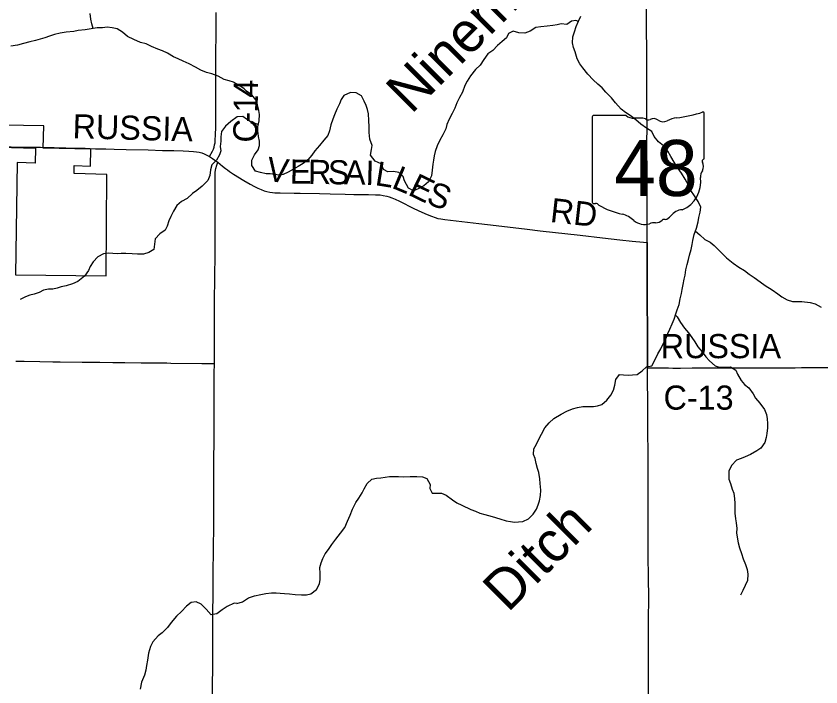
# Model space of a CAD drawing. Extents: x -87 to 2145, y -2128 to 440.
# Drawn here: x -9.26 to 40.7, y -1010.07 to -968.4 of the extents above; entities that cross this region are included whole.
import ezdxf

# ---------------------------------------------------------------- set-up
doc = ezdxf.new("R2010")
doc.units = 0
for name, color, linetype in [('GM_X_County_Road', 7, 'Continuous'), ('GM_X_County_Road_Text', 7, 'Continuous'), ('GM_X_County_Subdivision_Text', 7, 'Continuous'), ('GM_X_Minor_River', 7, 'Continuous'), ('GM_X_Minor_River_Text', 7, 'Continuous'), ('GM_X_State_Location', 7, 'Continuous'), ('GM_X_State_Route', 7, 'Continuous'), ('GM_X_State_Shield', 7, 'Continuous'), ('GM_X_Township_Road', 7, 'Continuous')]:
    doc.layers.add(name, color=color, linetype=linetype)

msp = doc.modelspace()

# ---------------------------------------------------------------- linework, layer by layer
at = {"layer": 'GM_X_County_Road'}
for points in [[(2.749, -977.127), (2.941, -976.786), (2.993, -976.663), (3.035, -976.537), (3.067, -976.408), (3.09, -976.277), (3.108, -976.096), (3.123, -975.8), (3.134, -975.274), (3.146, -973.896), (3.146, -972.863), (3.147, -972.223), (3.144, -971.304), (3.151, -970.501), (3.153, -969.763), (3.159, -968.697), (3.163, -968.172)], [(-15.533, -976.482), (-14.481, -976.477), (-13.497, -976.485), (-12.774, -976.489), (-11.478, -976.497), (-10.69, -976.507), (-9.558, -976.524), (-8.672, -976.537), (-7.737, -976.554), (-7.575, -976.558)], [(-7.575, -976.558), (-6.9, -976.575), (-5.423, -976.607), (-4.98, -976.617), (-4.324, -976.641), (-3.685, -976.659), (-3.176, -976.671), (-2.422, -976.693), (-1.06, -976.716), (-0.174, -976.746), (0.531, -976.76), (1.105, -976.776), (1.467, -976.789), (1.746, -976.807), (1.943, -976.831), (2.106, -976.862), (2.266, -976.906), (2.407, -976.956), (2.581, -977.038), (2.749, -977.127)], [(2.749, -977.127), (2.94, -977.243), (3.145, -977.39), (3.26, -977.482)], [(3.05, -989.978), (3.053, -989.142), (3.062, -988.043), (3.064, -987.288), (3.066, -986.386), (3.085, -984.402), (3.095, -983.434), (3.096, -982.236), (3.104, -981.006), (3.107, -979.317), (3.104, -978.332), (3.108, -978.121), (3.123, -977.976), (3.145, -977.866), (3.206, -977.663), (3.26, -977.482)], [(3.26, -977.482), (3.554, -977.719), (3.733, -977.863), (3.865, -977.962), (3.999, -978.057), (4.246, -978.22), (4.874, -978.609), (5.268, -978.846), (5.542, -978.998), (5.749, -979.1), (5.946, -979.184), (6.134, -979.249), (6.308, -979.299), (6.486, -979.338), (6.65, -979.364), (6.798, -979.377), (7.127, -979.386), (7.996, -979.395), (8.373, -979.402), (9.57, -979.431), (10.242, -979.452), (11.177, -979.469), (11.702, -979.479), (12.194, -979.487), (12.621, -979.491), (13.063, -979.497), (13.339, -979.513), (13.532, -979.539), (13.754, -979.589), (13.91, -979.634), (14.063, -979.689), (14.274, -979.777), (14.541, -979.901), (15.436, -980.348), (15.925, -980.583), (16.27, -980.737), (16.529, -980.842), (16.747, -980.919), (16.922, -980.968), (17.116, -981.008), (17.361, -981.044), (18.404, -981.165), (19.462, -981.297), (20.538, -981.417), (22.459, -981.65), (23.274, -981.739), (25.768, -982.018), (27.137, -982.178), (28.229, -982.301), (28.979, -982.383), (29.697, -982.454), (29.918, -982.476)], [(29.918, -982.476), (29.92, -983.466), (29.918, -984.336), (29.92, -984.992), (29.927, -985.812), (29.928, -986.451), (29.933, -987.649), (29.944, -988.698), (29.946, -990.254)], [(2.931, -1011.039), (2.94, -1009.957), (2.956, -1008.874), (2.955, -1008.004), (2.957, -1006.315), (2.965, -1005.331), (2.975, -1004.478), (2.98, -1003.297), (2.985, -1002.855), (2.995, -1001.706), (3.003, -1001.017), (3.007, -1000.525), (3.014, -999.738), (3.019, -997.671), (3.027, -996.654), (3.025, -995.785), (3.03, -994.981), (3.028, -994.472), (3.029, -994.128), (3.03, -993.981), (3.032, -993.079), (3.045, -991.734), (3.048, -990.602), (3.05, -989.978)], [(29.946, -990.254), (30.112, -990.255), (30.801, -990.259), (31.244, -990.263), (31.506, -990.264), (31.981, -990.265), (32.719, -990.258), (33.818, -990.258), (34.474, -990.255), (35.262, -990.254), (35.803, -990.258), (36.459, -990.254), (37.164, -990.25), (38.443, -990.248), (39.099, -990.247), (39.493, -990.242), (40.182, -990.24), (41.182, -990.232)]]:
    msp.add_lwpolyline(points, dxfattribs=at)
at = {"layer": 'GM_X_County_Subdivision_Text'}
msp.add_lwpolyline([(-10.304, -976.556), (-8.061, -976.603), (-8.069, -977.537), (-9.194, -977.506), (-9.291, -984.466), (-3.677, -984.536), (-3.628, -978.245), (-5.656, -978.19), (-5.643, -977.691), (-4.643, -977.717), (-4.615, -976.674), (-7.576, -976.613), (-7.539, -975.225), (-12.623, -975.146)], dxfattribs=at)
at = {"layer": 'GM_X_Minor_River'}
for points in [[(-4.478, -969.174), (-4.562, -968.89), (-4.617, -968.587), (-4.66, -968.244)], [(25.654, -968.738), (25.498, -968.675), (25.226, -968.72), (24.94, -968.936), (24.58, -968.888), (24.327, -968.943), (24.065, -968.988), (23.703, -969.031), (23.311, -969.063), (23.008, -969.107), (22.662, -969.341), (22.328, -969.465), (21.957, -969.448), (21.597, -969.339), (21.303, -969.494), (21.177, -969.754), (20.921, -969.98), (20.635, -970.236), (20.347, -970.542), (20.031, -970.757), (19.773, -971.104), (19.545, -971.452), (19.268, -971.729), (18.958, -972.125), (18.741, -972.453), (18.595, -972.712), (18.455, -973.122), (18.278, -973.461), (18.11, -973.79), (17.972, -974.129), (17.815, -974.448), (17.627, -974.817), (17.489, -975.137), (17.413, -975.417), (17.235, -975.776), (17.057, -976.105), (16.889, -976.464), (16.761, -976.814), (16.695, -977.084), (16.65, -977.355), (16.614, -977.606), (16.566, -977.978), (16.529, -978.32), (16.35, -978.699), (16.044, -978.954), (15.709, -979.129), (15.405, -979.253), (15.107, -979.086), (14.855, -978.637), (14.761, -978.363), (14.504, -978.126), (14.174, -978.059), (13.812, -978.082), (13.554, -977.935), (13.411, -977.58), (13.033, -977.411), (12.75, -977.042), (12.797, -976.7), (12.842, -976.45), (12.7, -976.054), (12.658, -975.64), (12.656, -975.277), (12.644, -974.894), (12.612, -974.48), (12.557, -974.217), (12.482, -973.964), (12.357, -973.699), (12.184, -973.353), (11.856, -973.175), (11.495, -973.147), (11.09, -973.33), (10.924, -973.589), (10.818, -973.849), (10.66, -974.188), (10.502, -974.537), (10.396, -974.797), (10.288, -975.167), (10.2, -975.528), (10.094, -975.818), (9.846, -976.115), (9.569, -976.441), (9.29, -976.778), (9.094, -977.036), (8.847, -977.333), (8.561, -977.559), (8.256, -977.744), (7.961, -977.919), (7.626, -978.103), (7.311, -978.248), (7.059, -978.283), (6.799, -978.247), (6.519, -978.211), (6.268, -978.196), (5.918, -978.118), (5.609, -978.031), (5.375, -977.683), (5.382, -977.351), (5.539, -977.032), (5.767, -976.704), (5.853, -976.444), (5.848, -976.172)], [(27.907, -991.32), (27.964, -990.969), (28.191, -990.671), (28.452, -990.697), (28.763, -990.703), (29.014, -990.688), (29.296, -990.664), (29.612, -990.429), (29.879, -990.182), (30.211, -990.119), (30.41, -989.73), (30.588, -989.381), (30.766, -989.063), (30.944, -988.684), (31.101, -988.405), (31.207, -988.115), (31.333, -987.856), (31.471, -987.516), (31.588, -987.227), (31.705, -986.897), (31.78, -986.646), (31.898, -986.327), (31.975, -985.976), (32.042, -985.645), (32.098, -985.384), (32.155, -985.083), (32.222, -984.752), (32.267, -984.491), (32.325, -984.16), (32.392, -983.829), (32.478, -983.528), (32.544, -983.248), (32.642, -982.897), (32.709, -982.596), (32.754, -982.346), (32.842, -981.965), (32.981, -981.585), (33.08, -981.194), (33.135, -980.923), (33.203, -980.592), (33.259, -980.281), (33.076, -979.925), (32.852, -979.577), (32.638, -979.241), (32.494, -978.915), (32.282, -978.528), (32.048, -978.161), (31.794, -977.813), (31.591, -977.476), (31.397, -977.119), (31.203, -976.803), (30.929, -976.455), (30.613, -976.217), (30.358, -975.889), (30.215, -975.564), (29.877, -975.365), (29.531, -975.126), (29.215, -974.848), (28.869, -974.579), (28.572, -974.401), (28.305, -974.184), (27.962, -973.794), (27.707, -973.486), (27.353, -973.126), (27.128, -972.87), (26.862, -972.623), (26.566, -972.365), (26.232, -972.005), (25.928, -971.626), (25.743, -971.36), (25.579, -971.065), (25.447, -970.629), (25.342, -970.365), (25.278, -970.061), (25.306, -969.689), (25.413, -969.389), (25.52, -969.049), (25.657, -968.729), (25.805, -968.4)], [(5.039, -973.073), (4.892, -972.916), (4.575, -972.698), (4.237, -972.51), (3.978, -972.424), (3.649, -972.337), (3.281, -972.139), (2.903, -972), (2.553, -971.913), (2.215, -971.755), (1.888, -971.567), (1.49, -971.368), (1.112, -971.209), (0.794, -971.052), (0.515, -970.945), (0.148, -970.716), (-0.18, -970.559), (-0.469, -970.452), (-0.857, -970.294), (-1.175, -970.136), (-1.534, -970.048), (-1.942, -969.869), (-2.34, -969.68), (-2.656, -969.402), (-2.983, -969.194), (-3.303, -969.127), (-3.613, -969.101), (-3.885, -969.136), (-4.226, -969.139), (-4.478, -969.174), (-4.961, -969.266), (-5.403, -969.307), (-5.675, -969.352), (-6.158, -969.403), (-6.53, -969.456), (-6.873, -969.54), (-7.186, -969.645), (-7.469, -969.75), (-7.762, -969.845), (-8.044, -969.93), (-8.397, -970.014), (-8.801, -970.117), (-9.173, -970.201), (-9.586, -970.263)], [(5.848, -976.172), (5.794, -975.889), (5.741, -975.535), (5.746, -975.284), (5.825, -974.902), (5.843, -974.52), (5.818, -974.268), (5.735, -973.923), (5.621, -973.609), (5.366, -973.291), (5.039, -973.073)], [(5.043, -974.816), (4.808, -974.637), (4.457, -974.661), (4.08, -974.956), (3.733, -975.241), (3.496, -975.569), (3.459, -975.911), (3.444, -976.173), (3.417, -976.515), (3.442, -976.767), (3.377, -977.028), (3.19, -977.347), (2.903, -977.653), (2.817, -977.964), (2.77, -978.296), (2.654, -978.616), (2.296, -978.962), (1.959, -979.237), (1.695, -979.433), (1.358, -979.729), (1.013, -979.924), (0.717, -980.18), (0.519, -980.529), (0.343, -980.848), (0.227, -981.118), (0.12, -981.448), (0.005, -981.708), (-0.331, -981.933), (-0.618, -982.23), (-0.665, -982.581), (-0.711, -982.903), (-1.016, -983.089), (-1.359, -983.183), (-1.72, -983.196), (-2.061, -983.179), (-2.441, -983.141), (-2.743, -983.155), (-2.994, -983.17), (-3.244, -983.155), (-3.525, -983.13), (-3.827, -983.164), (-4.192, -983.359), (-4.479, -983.665), (-4.655, -983.954), (-4.76, -984.214), (-5.018, -984.552), (-5.426, -984.896), (-5.75, -985.041), (-6.143, -985.164), (-6.456, -985.229), (-6.718, -985.314), (-6.97, -985.36), (-7.241, -985.374), (-7.553, -985.419), (-7.817, -985.565), (-8.14, -985.669), (-8.402, -985.744), (-8.665, -985.84), (-9.01, -986.015)], [(5.777, -975.132), (5.65, -975.09), (5.341, -974.993), (5.043, -974.816)], [(32.916, -981.763), (33.193, -981.992), (33.488, -982.29), (33.827, -982.438), (34.083, -982.655), (34.516, -983.087), (34.84, -983.427), (35.266, -983.748), (35.602, -983.996), (35.969, -984.216), (36.245, -984.433), (36.562, -984.651), (36.938, -984.921), (37.245, -985.139), (37.681, -985.41), (38.028, -985.659), (38.285, -985.845), (38.602, -986.023), (38.931, -986.141), (39.203, -986.136), (39.514, -986.133), (40.035, -986.204), (40.345, -986.271), (40.722, -986.49)], [(31.678, -986.972), (31.781, -987.09), (31.995, -987.447), (32.239, -987.784), (32.474, -988.071), (32.698, -988.368), (32.874, -988.633), (33.068, -988.94), (33.342, -989.268), (33.567, -989.564), (33.783, -989.821), (34.138, -990.13), (34.397, -990.206), (34.749, -990.203), (35.101, -990.191), (35.418, -990.388), (35.533, -990.643), (35.746, -991.03), (35.962, -991.286), (36.238, -991.503), (36.502, -991.861), (36.647, -992.136), (36.911, -992.444), (37.194, -992.843), (37.318, -993.147), (37.373, -993.42), (37.397, -993.703), (37.391, -993.985), (37.354, -994.336), (37.298, -994.587), (37.232, -994.898), (36.973, -995.235), (36.719, -995.411), (36.342, -995.635), (36.008, -995.779), (35.745, -995.884), (35.462, -995.979), (35.163, -996.315), (34.995, -996.664), (34.98, -996.916), (34.985, -997.177), (35.09, -997.431), (35.203, -997.786), (35.288, -998.04), (35.331, -998.393), (35.365, -998.656), (35.369, -998.978), (35.362, -999.29), (35.395, -999.623), (35.45, -999.876), (35.483, -1000.229), (35.467, -1000.51), (35.502, -1000.763), (35.565, -1001.117), (35.658, -1001.441), (35.782, -1001.776), (35.885, -1002.11), (36.028, -1002.475), (36.123, -1002.779), (36.157, -1003.062), (36.149, -1003.454), (36.011, -1003.774), (35.864, -1004.093), (35.718, -1004.372)], [(4.444, -1004.888), (4.787, -1004.795), (5.164, -1004.541), (5.549, -1004.418), (5.942, -1004.336), (6.255, -1004.262), (6.587, -1004.218), (6.888, -1004.225), (7.139, -1004.24), (7.41, -1004.266), (7.72, -1004.292), (8.071, -1004.34), (8.452, -1004.348), (8.764, -1004.344), (9.036, -1004.29), (9.383, -1004.015), (9.581, -1003.677), (9.617, -1003.406), (9.615, -1003.033), (9.593, -1002.65), (9.689, -1002.36), (9.775, -1002.09), (9.922, -1001.801), (10.128, -1001.544), (10.346, -1001.226), (10.594, -1000.889), (10.883, -1000.512), (11.141, -1000.175), (11.32, -999.776), (11.478, -999.407), (11.617, -999.027), (11.836, -998.619), (12.013, -998.35), (12.22, -998.022), (12.346, -997.763), (12.544, -997.435), (12.831, -997.159), (13.123, -997.105), (13.385, -997.08), (13.647, -997.035), (13.919, -997), (14.21, -996.996), (14.491, -997.012), (14.782, -997.018), (15.204, -996.997), (15.616, -996.996), (15.977, -997.033), (16.246, -997.13), (16.439, -997.496), (16.434, -997.748), (16.569, -998.033), (16.9, -998.04), (17.151, -998.035), (17.439, -998.172), (17.835, -998.462), (18.102, -998.639), (18.411, -998.786), (18.968, -999.05), (19.266, -999.166), (19.535, -999.283), (19.835, -999.36), (20.294, -999.49), (20.763, -999.641), (21.162, -999.76), (21.432, -999.806), (21.683, -999.841), (21.934, -999.826), (22.196, -999.802), (22.541, -999.628), (22.848, -999.352), (23.045, -999.034), (23.151, -998.764), (23.237, -998.514), (23.304, -998.173), (23.311, -997.851), (23.28, -997.427), (23.245, -997.145), (23.183, -996.761), (23.108, -996.497), (23.034, -996.194), (22.961, -995.88), (22.866, -995.626), (22.873, -995.274), (23.04, -994.985), (23.217, -994.646), (23.364, -994.378), (23.563, -993.979), (23.84, -993.672), (24.117, -993.396), (24.585, -993.134), (24.93, -992.94), (25.275, -992.806), (25.598, -992.722), (25.931, -992.648), (26.593, -992.662), (26.845, -992.617), (27.108, -992.522), (27.405, -992.266), (27.672, -991.96), (27.83, -991.63), (27.907, -991.32)], [(4.444, -1004.888), (4.27, -1004.865), (3.854, -1005.068), (3.539, -1005.283), (3.193, -1005.538), (2.851, -1005.592), (2.536, -1005.253), (2.221, -1004.935), (1.913, -1004.788), (1.611, -1004.832), (1.316, -1005.058), (1.018, -1005.385), (0.692, -1005.68), (0.373, -1006.067), (0.136, -1006.375), (-0.181, -1006.711), (-0.436, -1006.897), (-0.774, -1007.273), (-0.911, -1007.572), (-1.029, -1007.983), (-1.108, -1008.404), (-1.164, -1008.736), (-1.21, -1009.027), (-1.296, -1009.337), (-1.465, -1009.777), (-1.554, -1010.208)]]:
    msp.add_lwpolyline(points, dxfattribs=at)
at = {"layer": 'GM_X_State_Route'}
for points in [[(29.918, -982.244), (29.916, -981.498), (29.917, -980.366), (29.91, -979.399), (29.911, -978.89), (29.912, -978.004), (29.904, -976.758), (29.905, -976.217), (29.909, -975.364), (29.901, -974.264), (29.899, -972.854), (29.899, -971.64), (29.892, -970.492), (29.883, -969.245), (29.88, -968.426), (29.885, -967.54), (29.884, -966.113), (29.879, -964.85), (29.874, -963.685), (29.876, -963.474)], [(29.918, -982.476), (29.918, -982.351), (29.918, -982.244)], [(29.946, -990.254), (29.944, -988.698), (29.933, -987.649), (29.928, -986.451), (29.927, -985.812), (29.92, -984.992), (29.918, -984.336), (29.92, -983.466), (29.918, -982.476)], [(30.002, -1010.841), (29.998, -1010.054), (29.997, -1009.021), (30.002, -1007.364), (30.003, -1006.15), (30.015, -1004.296), (30.005, -1003.525), (29.983, -1001.656), (29.981, -1000.491), (29.974, -998.277), (29.975, -996.932), (29.973, -996.276), (29.971, -995.275), (29.969, -994.488), (29.963, -993.176), (29.953, -992.11), (29.948, -991.273), (29.946, -990.273), (29.946, -990.254)]]:
    msp.add_lwpolyline(points, dxfattribs=at)
at = {"layer": 'GM_X_State_Shield'}
for p, q in [((26.506, -974.671), (26.506, -979.954)), ((28.613, -974.58), (26.574, -974.58)), ((33.466, -977.213), (33.466, -974.449)), ((33.466, -977.212), (33.466, -977.213))]:
    msp.add_line(p, q, dxfattribs=at)
for centre, radius, start, end in [((26.585, -974.659), 0.0806, 98.1301, 188.1301), ((29.098, -973.966), 0.782, 231.6195, 271.1119), ((29.357, -977.546), 2.808, 80.4867, 94.9883), ((31.928, -976.193), 1.485, 97.3462, 120.7689), ((30.987, -967.377), 7.382, 275.8445, 288.9065), ((33.389, -974.437), 0.0775, 351.8621, 97.738), ((29.995, -974.632), 0.226, 219.7921, 297.1024), ((30.326, -975.243), 0.469, 54.4667, 119.1411), ((30.932, -974.405), 0.564, 233.8562, 294.8282), ((33.384, -977.223), 0.0829, 289.6038, 7.7341), ((33.448, -977.415), 0.12, 107.944, 210.337), ((32.686, -977.765), 0.72, 340.033, 23.6496), ((33.744, -978.369), 0.524, 136.8065, 186.9296), ((31.4, -978.721), 1.846, 292.3089, 8.9858), ((26.586, -979.965), 0.0814, 171.9584, 258.3066), ((26.598, -979.425), 0.621, 267.339, 280.6039), ((26.725, -980.259), 0.224, 29.7484, 93.2717), ((29.552, -975.512), 5.331, 240.4129, 257.1985), ((27.963, -982.327), 1.668, 47.1842, 75.836), ((32.179, -981.437), 1.011, 94.4031, 142.5768), ((29.766, -980.285), 1.058, 230.7004, 286.2918), ((30.378, -982.111), 0.87, 85.6951, 111.2099), ((30.455, -980.681), 0.564, 268.777, 315.5493), ((30.965, -981.192), 0.159, 65.7517, 132.6484), ((30.898, -980.466), 0.597, 282.8732, 323.2771)]:
    msp.add_arc(centre, radius, start, end, dxfattribs=at)
at = {"layer": 'GM_X_Township_Road'}
msp.add_lwpolyline([(-9.272, -989.846), (-8.747, -989.847), (-7.795, -989.859), (-6.976, -989.873), (-6.516, -989.877), (-5.155, -989.892), (-4.056, -989.903), (-3.252, -989.915), (-3.022, -989.918), (-2.793, -989.921), (-2.498, -989.925), (-1.497, -989.934), (-0.398, -989.948), (0.094, -989.952), (0.34, -989.956), (2.276, -989.974), (2.75, -989.976), (2.913, -989.977), (3.05, -989.978)], dxfattribs=at)

# ---------------------------------------------------------------- texts
at = {"layer": 'GM_X_County_Road_Text'}
for s, rotation, p in [('4', 89.6157, (5.75, -973.477)), ('1', 89.5847, (5.743, -974.402)), ('RUSSIA', 358.4567, (-5.765, -975.992)), ('-', 89.4935, (5.738, -975.021)), ('C', 88.626, (5.708, -976.277)), ('V', 352.6378, (6.23, -978.627)), ('E', 359.3575, (7.73, -978.809)), ('R', 358.9969, (8.85, -978.822)), ('S', 358.995, (10.081, -978.843)), ('A', 358.9563, (11.093, -978.861)), ('I', 358.5011, (12.41, -978.885)), ('L', 350.9129, (12.973, -978.896)), ('L', 337.2527, (13.99, -979.048)), ('E', 334.0847, (15.005, -979.473)), ('S', 338.6692, (16.134, -980.015)), ('RD', 353.6053, (23.852, -981.188)), ('RUSSIA', 359.9993, (30.76, -989.654)), ('C-13', 0, (30.936, -992.851))]:
    msp.add_text(s, height=1.5, rotation=rotation, dxfattribs=at).set_placement(p)
at = {"layer": 'GM_X_Minor_River_Text'}
for s, height, rotation, p in [('Ninemile', 2.4994, 45.0067, (15.272, -974.547)), ('Ditch', 2.499, 44.9947, (21.269, -1005.505))]:
    msp.add_text(s, height=height, rotation=rotation, dxfattribs=at).set_placement(p)
at = {"layer": 'GM_X_State_Location'}
for s, p in [('s', (29.908, -977.664)), ('r', (29.907, -977.664))]:
    msp.add_text(s, height=0.005, dxfattribs=at).set_placement(p)
msp.add_text('48', height=0.005, rotation=0, dxfattribs=at).set_placement((28.648, -978.027))
at = {"layer": 'GM_X_State_Shield'}
msp.add_text('48', height=3.4805, dxfattribs=at).set_placement((27.871, -979.581))

doc.saveas('drawing.dxf')
